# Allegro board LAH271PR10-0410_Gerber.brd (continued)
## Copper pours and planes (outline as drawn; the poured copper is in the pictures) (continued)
N23832788 on BOTTOM: 44.56,21.27 44.4,21.24 44.25,21.27 44.22,21.29 44.2,21.29 44.06,21.43 44.06,23.02 44.27,23.23 45.14,23.23 45.15,23.23 45.41,23.26 45.58,23.46 45.58,23.47 45.99,23.88 46.24,23.88 47.64,25.28 48.06,25.28 49.04,26.26 49.71,26.26 50.93,26.26 51.21,25.99 51.4,25.99 51.62,25.91 51.83,25.99 52.3,25.99 52.38,25.91 52.38,25.37 52.24,25.23 51.64,25.23 50.95,24.54 48.88,24.54 48.57,24.22 48.26,24.22 47.91,23.87 47.91,22.45 47.42,21.96 47.42,21.48 47.26,21.31 45.34,21.31 45.31,21.29 44.59,21.29
N25195948 on TOP (solid shape): 308.38,42.33 308.38,40.02 308.55,39.85 308.55,39.26 308.48,39.19 307.51,39.19 307.23,39.47 307.23,42.38 307.31,42.45 308.25,42.45
N26822390 on TOP (solid shape): 292.15,30.78 292.15,29.89 292.04,29.78 291.17,29.78 290.85,30.11 290.01,30.11 289.96,30.15 289.11,30.15 289.07,30.19 289.07,30.37 289.11,30.41 289.93,30.41 289.98,30.37 290.46,30.37 290.5,30.37 290.57,30.44 290.84,30.44 291.06,30.66 291.12,30.71 291.17,30.76 291.25,30.84 292.09,30.84
N27028301 on TOP (solid shape): 279.06,81.62 279.06,81 278.71,80.65 278.28,80.65 277.56,79.94 277.56,79.36 277.56,79.36 277.56,78.91 277.47,78.82 277.01,78.82 276.96,78.88 276.96,79.48 276.94,79.48 276.89,79.53 276.89,80.86 276.94,80.91 277.33,80.91 277.53,81.11 277.65,81.11 277.66,81.1 278.04,81.17 278.13,81.54 278.12,81.58 278.3,81.76 278.92,81.76
N42077965 on TOP (solid shape): 248.18,141.24 248.18,140.58 249.01,139.75 249.01,139 248.96,138.95 248.72,138.95 248.64,139.03 248.64,139.61 248.31,139.94 247.79,139.94 247.21,140.53 247.21,141.25 247.27,141.31 248.11,141.31
N42077969 on TOP (solid shape): 249.43,141.24 249.43,140.58 249.88,140.12 249.88,139.82 249.99,139.71 249.99,139.03 249.91,138.95 249.73,138.95 249.63,139.05 249.63,139.73 249.51,139.84 249.17,139.84 248.39,140.63 248.39,141.24 248.44,141.29 249.38,141.29
N42077993 on TOP (solid shape): 250.89,142.67 250.89,140.58 251.08,140.39 251.08,139.85 251.01,139.78 251.01,139.04 250.9,138.94 250.78,138.94 250.65,139.06 250.65,140.16 250.32,140.49 249.76,140.49 249.63,140.61 249.63,142.66 249.71,142.74 250.82,142.74
N42078041 on TOP (solid shape): 240.53,141.14 240.53,140.39 241.32,139.6 241.32,138.95 241.21,138.85 241.06,138.85 240.99,138.93 240.99,139.51 240.75,139.74 240.19,139.74 240.1,139.84 240.09,139.84 239.51,140.41 239.51,141.19 239.54,141.21 240.45,141.21
N42078055 on TOP (solid shape): 241.75,141.14 241.75,140.36 242.16,139.95 242.16,139.72 242.31,139.58 242.31,138.93 242.23,138.85 242.05,138.85 241.95,138.95 241.95,139.54 241.68,139.81 241.43,139.81 240.71,140.53 240.71,141.14 240.76,141.19 241.7,141.19
N42078421 on TOP (solid shape): 249.42,142.83 249.42,142.12 249.37,142.07 247.28,142.07 247.23,142.12 247.23,142.78 247.33,142.88 249.36,142.88
N42078543 on BOTTOM (solid shape): 252.82,134.7 252.82,133.71 252.8,133.68 251.63,133.68 251.55,133.61 251.55,133.1 251.45,133 250.46,133 250.36,133.1 250.36,134.7 250.46,134.8 252.72,134.8
N42078657 on TOP (solid shape): 241.66,142.5 241.66,141.79 241.61,141.74 239.53,141.74 239.48,141.79 239.48,142.45 239.58,142.55 241.61,142.55
N42078671 on TOP (solid shape): 243.21,142.55 243.21,140.45 243.21,140.45 243.21,140.28 243.4,140.1 243.4,139.78 243.32,139.71 243.32,138.93 243.22,138.83 243.09,138.83 242.97,138.95 242.97,140.04 242.69,140.32 242.05,140.32 241.95,140.42 241.95,142.54 242.05,142.63 243.12,142.63
N42078715 on BOTTOM (solid shape): 245.18,134.69 245.18,134.19 245.19,134.19 245.19,134.04 245.09,133.94 244.24,133.94 244,133.71 244,133.29 243.88,133.17 242.82,133.17 242.72,133.27 242.72,134.79 242.79,134.85 245.02,134.85
N51087553 on TOP (solid shape): 309.24,32.22 309.24,30.65 309.85,30.03 309.85,29.39 309.78,29.32 308.78,29.32 308.66,29.43 308.31,29.43 307.99,29.75 307.99,32.25 308.11,32.38 309.08,32.38
N51088117 on TOP (solid shape): 311.14,24.98 311.14,24.41 311.09,24.37 308.99,24.37 308.91,24.45 308.91,25.05 308.91,25.05 311.07,25.05
N51093717 on BOTTOM (solid shape): 68.37,15.52 68.37,14.76 68.26,14.66 67.62,14.66 67.6,14.69 67.56,14.71 66.23,16.03 65.11,16.03 65.04,16.11 65.04,17.02 65.1,17.07 66.82,17.07
N51093811 on BOTTOM (solid shape): 73.42,15.78 73.42,13.63 73.35,13.56 72.74,13.56 72.71,13.59 72.71,15.77 72.8,15.85 73.34,15.85
N51093813 on TOP (solid shape): 111.22,11.28 111.22,10.52 110.75,10.05 110.75,9.92 110.47,9.64 110.47,9.13 111.13,8.48 111.23,8.48 111.47,8.23 111.47,7.85 111.29,7.68 110.61,7.68 110.57,7.72 110.46,7.72 109.82,8.36 109.82,10.08 110.22,10.48 110.22,11.22 110.35,11.35 111.15,11.35
N51093813 on BOTTOM (solid shape): 111.06,11.41 111.06,9.8 110.92,9.67 110.02,9.67 109.83,9.86 109.83,11.28 110.04,11.49 110.98,11.49
N51093922 on TOP (solid shape): 111.21,3.34 112.43,3.34 112.51,3.26 112.51,2.62 112.44,2.54 110.15,2.54 110.05,2.65 110.05,3.28 110.15,3.38 111.16,3.38
N61688512 on TOP (solid shape): 149.1,12.44 149.1,10.49 148.96,10.35 148.16,10.35 147.86,10.65 147.86,12.22 148.23,12.59 148.95,12.59
N61690744 on TOP (solid shape): 134.36,7.64 134.36,7.01 134.19,6.84 132.77,6.84 132.59,7.02 132.59,7.83 132.78,8.02 133.97,8.02
N61692023 on TOP (solid shape): 225.06,138.69 225.06,138.03 225.67,137.41 225.67,136.5 225.58,136.4 225.44,136.4 225.34,136.5 225.34,137.08 225.12,137.3 224.56,137.3 224.04,137.82 224.04,138.74 224.07,138.76 224.98,138.76
N61692025 on TOP (solid shape): 226.25,138.71 226.25,138.05 226.66,137.64 226.66,137.56 226.65,137.48 226.66,137.4 226.66,136.49 226.58,136.4 226.45,136.4 226.35,136.5 226.35,137.16 226.2,137.32 226,137.32 225.21,138.1 225.21,138.71 225.26,138.76 226.2,138.76
N61692045 on TOP (solid shape): 227.69,140.2 227.69,138.04 227.8,137.93 227.8,137.29 227.66,137.15 227.66,136.49 227.57,136.4 227.44,136.4 227.35,136.49 227.35,137.27 227.41,137.32 227.41,137.66 227.12,137.95 226.56,137.95 226.43,138.08 226.43,140.21 226.53,140.31 227.57,140.31
N61692081 on TOP (solid shape): 226.24,140.05 226.24,139.34 226.19,139.29 224.11,139.29 224.06,139.34 224.06,140.05 224.11,140.1 226.19,140.1
N61692131 on BOTTOM (solid shape): 229.7,132.24 229.7,131.72 229.59,131.61 228.65,131.61 228.38,131.34 228.38,130.73 228.31,130.66 227.28,130.66 227.26,130.68 227.26,132.3 227.31,132.34 228.38,132.34 228.41,132.37 229.57,132.37
N61692600 on TOP (solid shape): 234.02,141.12 234.02,140.46 234.4,140.08 234.38,140.04 234.37,139.78 234.54,139.58 234.58,139.56 234.58,138.91 234.5,138.84 234.32,138.84 234.22,138.94 234.22,139.46 234.17,139.51 234.16,139.52 234.11,139.59 234.04,139.65 234.03,139.65 233.99,139.69 233.8,139.69 233.51,139.98 233.43,140.11 233.3,140.19 232.98,140.51 232.98,141.12 233.03,141.17 233.97,141.17
N61692604 on TOP (solid shape): 232.79,141.12 232.79,140.46 233.58,139.68 233.58,138.94 233.48,138.84 233.32,138.84 233.25,138.91 233.25,139.5 232.92,139.83 232.21,139.83 231.81,140.23 231.81,141.15 231.85,141.2 232.72,141.2
N61692626 on TOP (solid shape): 234,142.55 234,141.84 233.95,141.79 231.86,141.79 231.81,141.84 231.81,142.55 231.87,142.6 233.94,142.6
N61692634 on TOP (solid shape): 235.46,142.5 235.46,140.47 235.65,140.28 235.65,139.68 235.58,139.61 235.58,138.93 235.47,138.83 235.35,138.83 235.22,138.96 235.22,139.92 234.77,140.38 234.33,140.38 234.2,140.51 234.2,142.54 234.29,142.63 235.33,142.63
N61692676 on BOTTOM (solid shape): 237.49,134.73 237.49,134.18 237.33,134.02 236.44,134.02 236.26,133.84 236.26,133.28 236.16,133.18 235.13,133.18 235.03,133.28 235.03,134.74 235.12,134.83 237.39,134.83
N63206214 on BOTTOM (solid shape): 8.22,23.94 8.22,23.08 8.47,22.83 9.12,22.83 9.26,22.69 9.26,22.09 9.19,22.01 8.6,22.01 8.34,22.27 6.51,22.27 6.29,22.49 6.29,23.91 6.51,24.13 8.03,24.13
N63359909 on TOP (solid shape): 39.65,27.12 39.99,27.12 39.99,27.12 40.86,27.12 40.92,27.06 40.92,25.61 40.82,25.52 39.98,25.52 39.77,25.73 38.82,25.73 38.68,25.87 38.68,27.14 38.79,27.25 39.52,27.25
N63361205 on BOTTOM (solid shape): 26.12,22.13 26.12,21.17 26.02,21.07 25.49,21.07 25.34,21.22 25.34,21.64 25.07,21.92 23.94,21.92 23.88,21.97 23.88,22.49 23.98,22.59 24.73,22.59 24.85,22.71 25.54,22.71
N64433264 on TOP (solid shape): 96.54,18.89 96.54,18.4 96.36,18.22 94.09,18.22 93.78,18.54 93.78,18.92 93.97,19.1 96.32,19.1
N64440771 on TOP (solid shape): 78.7,25.73 78.7,24.72 78.34,24.36 77.4,24.36 76.9,24.86 75.71,24.86 75.55,25.02 75.55,25.62 75.83,25.89 77.5,25.89 77.65,26.04 78.39,26.04
N67988280 on BOTTOM (solid shape): 343.99,26.39 343.99,25.66 343.88,25.55 343.48,25.55 343.4,25.56 343.31,25.55 341.91,25.55 341.78,25.68 341.78,26.3 342,26.52 343.86,26.52

Small or netless copper shapes (teardrops, artwork), in the pictures only: 286 on TOP, 34 on BOTTOM, 2 on IN3

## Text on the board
Ref Des/Silkscreen Bottom: JDGFF4.1 | JDGFF1.1 | JDGFF3.1 | JDGFF2.1 | PWB P/N: | COPYRIGHT 2019 | REV:A00 | ALL RIGHT RESERVED | H16 | H17
User.Comments: CR_1_1 | CR_UNNAMED_1 | CR_1_2 | CR_1_4 | CR_2_4 | CR_UNNAMED_5 | CR_UNNAMED_4 | LA-H271P | 2020-04-10 | 2019-04-10 | EDA50 | Minjia | REV:1.0(A00)
Ref Des/Silkscreen Top: H4 | H28 | H5 | H15 | H14
GND4: GND4
GND5: GND5
USER_PART_NUM_BOTTOM: LAYER | NO. | L1 | L2 | L3 | L4 | L5 | L6 | L7 | L8 | L9 | L10 | L11 | L12 | LA-H271P | GND4 | GND3 | GND5 | IN4 | IN3 | VCC | BOT | GND2 | TOP | GND1 | IN2 | IN1
User.43: trace Width | Width/space | REF | L2-GND1 | L3-IN1 | L4-GND2 | L1-TOP | L5-IN2 | L6-GND3 | L11-GND5 | L9-GND4 | L7-VCC | L8-IN3 | L12-BOT | L10-IN4 | 8.3mil | 7.4mil | 6.6mil | 6mil | 5mil | 5.5mil | 4.5mil | 3.2 mil | 4.3mil | 4mil | 5.2/3.5mil | 5.5/4mil | 4.7/4mil | 6/5mil | 4/3.5mil | 4.3/4.2mil | 3.7/4mil | 4/3.4mil | 4.3/5.2mil | 4/4mil | 4.3/6mil | 4/4.5mil | 3.2/18 mil | 4.3/16mil | 4/18mil | L9/L11 | L7/L9 | L2/L4 | L4/L6 | L11 | L2 | 9/3.5mil | L10 | L3 | L12_1_45mm(Hoz 1oz 2oz)(Top G-V IN1 G-V  IN2 G-V G-V IN3 G-V IN4 G-V Bot)_180820 | LAYER | NAME | STACKUP: 12 LAYER | 35 ohm | 40 ohm | THICKNESS=1.45mm | 42 ohm | 50 ohm | 75 ohm | 85 ohm | 88 ohm | 90 ohm | 100 ohm
User.45: stack-up setting ok | FIGURE | SIZE | 8.0 | 20.0 | 35.0 | 39.0 | 83.0 | 98.0 | 126.0 | 130.0 | 146.0 | 28.0 | 31.0 | 43.0 | 47.0 | 63.0 | 106.0 | 31.0x28.0 | 47.0x26.0 | 51.0x28.0 | 55.0x24.0 | 59.0x24.0 | 67.0x31.0 | 69.0x20.0 | 75.0x28.0 | 79.0x28.0 | 94.0x28.0 | 142.0x83.0 | 33.0x31.0 | 197.0x98.0 | DRILL CHART: TOP to BOTTOM | ALL UNITS ARE IN MILS | TOLERANCE | +3.0/-3.0 | +2.0/-2.0 | PLATED | NON-PLATED | QTY | 9170 | 33 | 28 | 5 | 1 | 13 | 2 | 4 | 9 | 12 | 6 | 8
